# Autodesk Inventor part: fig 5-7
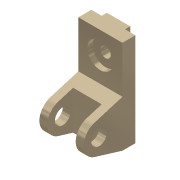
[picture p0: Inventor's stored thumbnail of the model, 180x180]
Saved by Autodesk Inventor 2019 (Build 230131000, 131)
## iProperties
Shininess: 65.0
Angle Display Precision: 2
Document Length Units: 11269
Document Angle Units: 11279
Document Time Units: 11290
Document Mass Units: 11283
Document Length Units Precision: 3
Document Angle Units Precision: 2
Compacted: False
Created: 2001-11
Part Number: fig 5-7
Document SubType Name: Modeling
Designer: Renu Muthoo
Density: 1 g/cm^3
Material: Generic
Appearance: Metal-Titanium (Polished)
Density: 0.0
Volumn: 0.0
Area: 0.0
PropertySet Name: Model Information
Control State: 0
Master: False
Checked Out: False
Author: Renu Muthoo
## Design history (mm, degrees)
node "Sketch1"
sketch "Sketch2"
  geometry: L1 (33.257, 104.664)-(33.257, -75.336); L2 (33.257, -75.336)-(8.257, -75.336); L3 (8.257, -75.336)-(-45.451, -59.045); L4 (-45.451, -1.628)-(8.257, 14.664); L5 (8.257, 14.664)-(8.257, 104.664); L6 (8.257, 104.664)-(33.257, 104.664); C1 r 15 at (-36.743, -30.336); A1 r 30 centre (-36.743, -30.336) between (-45.451, -1.628) and (-45.451, -59.045)
  constraints: 12 end point, 2 centre point, 2 equal length, 2 parallel, 2 point on circle, 2 tangent, 1 coincident, 1 perpendicular, 1 vertical
  dimensions: "d0" = 180 distance of L1.start L1.end; "d1" = 30 radius of A1; "d2" = 25 distance of L5.end L1.start; "d3" = 45 distance from line of L2 A1.centre; "d4" = 70 distance from line of L1 A1.centre; "d5" = 30 diameter of C1
extrude "Extrusion1" new body sketch "Sketch2" distance "d6" = 85; taper "d7" = 0 deg
workplane "Work Plane1"
sketch "Sketch3"
  geometry: L1 (15, 62.364)-(70, 62.364); L2 (70, 62.364)-(70, -52.386); L3 (70, -52.386)-(15, -52.386); L4 (15, -52.386)-(15, 62.364); L5 (0, -45)-(0, -28.708) reference
  constraints: 8 end point, 2 parallel, 1 horizontal, 1 perpendicular
  dimensions: "d8" = 55 distance of L1.start L1.end; "d9" = 15 distance between parallel lines of L5 L4
extrude "Extrusion2" cut sketch "Sketch3" distance "d10" = 50; taper "d11" = 0 deg
sketch "Sketch4"
  geometry: L1 (0, 25)-(85, 25) reference; L2 (0, 0)-(0, 25) reference; L3 (20, 25)-(65, 25); L4 (65, 25)-(65, 35); L5 (65, 35)-(20, 35); L6 (20, 35)-(20, 25)
  constraints: 8 end point, 2 parallel, 1 horizontal, 1 perpendicular, 1 point on line
  dimensions: "d12" = 45 distance of L4.end L5.end; "d13" = 10 distance of L3.end L4.end; "d14" = 20 distance between parallel lines of L2 L6
extrude "Extrusion3" join sketch "Sketch4" stored distance "d15" = 50; taper "d16" = 0 deg
sketch "Sketch5"
  geometry: L1 (85, 0)-(85, 90) reference; L2 (0, 90)-(85, 90) reference; 1 further point
  dimensions: "d17" = 42 distance from line of L2 point (42.5, 48); "d18" = 42.5 distance from line of L1 point (42.5, 48)
hole "Hole1" sketch "Sketch5" at (42.5, 48) diameter "d19" = 20; stored, may be unused: countersink angle "d23" = 82 deg, drill point angle "d25" = 118 deg; dims "d20" = 6, "d21" = 50, "d22" = 10, "d24" = 8
body "Solid1"
